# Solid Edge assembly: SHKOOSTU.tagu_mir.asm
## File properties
Author: Türk
Template: Iso Assembly.asm
Last saved by: Türk
Revision: 2
Application: Solid Edge
Username: Türk
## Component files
Shockabsorber.par
ShKolvikoostu.asm
Shkaan.par
Poldikoostu5.asm
Taguminevedru_mir.par
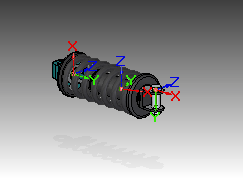
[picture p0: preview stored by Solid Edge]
